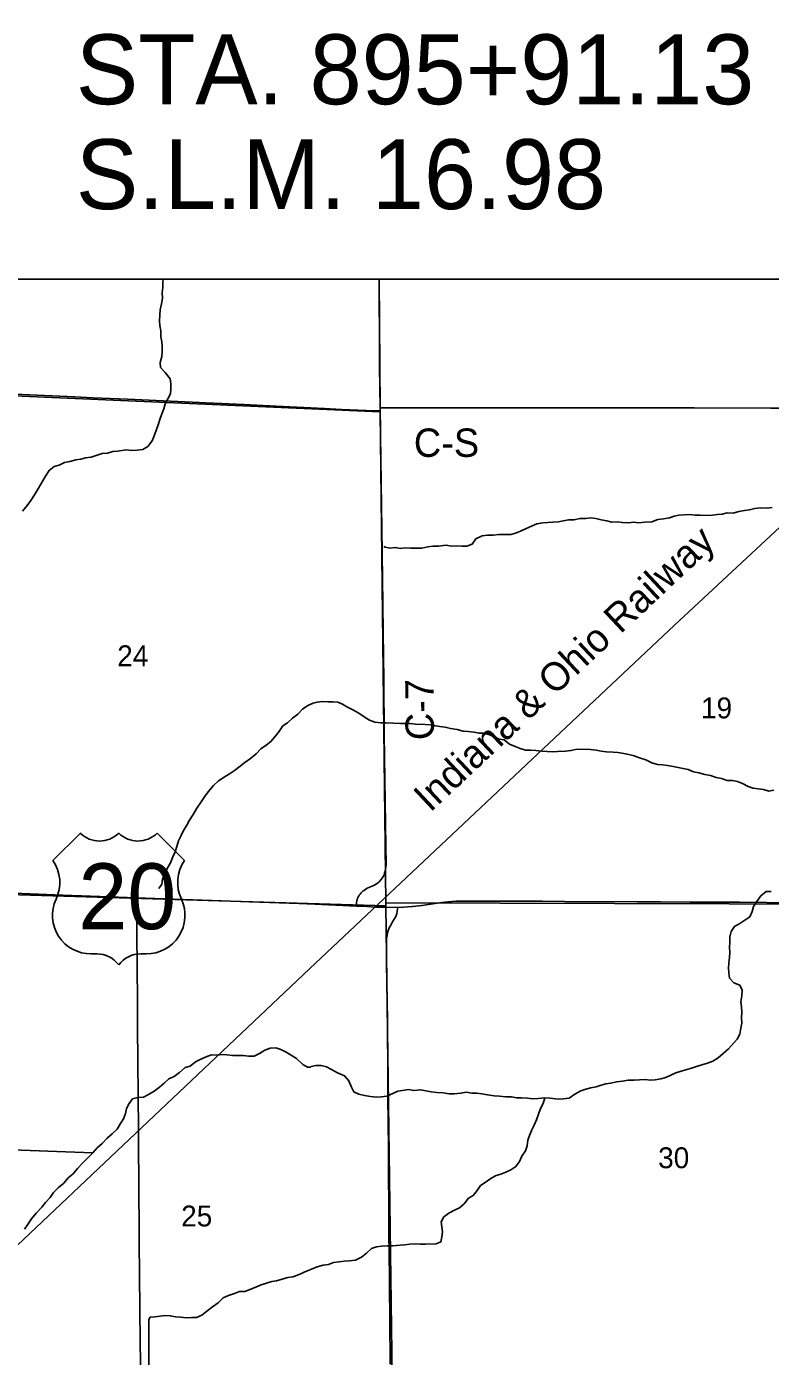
# Model space of a CAD drawing. Extents: x 0 to 34, y 0 to 22.
# Drawn here: x 28.195 to 29.684, y 16.699 to 19.362 of the extents above; entities that cross this region are included whole.
import ezdxf

# ---------------------------------------------------------------- set-up
doc = ezdxf.new("R2010")
doc.units = 0
for name, color, linetype in [('GM_X_County_Road', 7, 'Continuous'), ('GM_X_County_Road_Text', 7, 'Continuous'), ('GM_X_Minor_River', 7, 'Continuous'), ('GM_X_Rail_Line', 7, 'Continuous'), ('GM_X_Rail_Line_Text', 7, 'Continuous'), ('GM_X_Section', 7, 'Continuous'), ('GM_X_Section_Text', 7, 'Continuous'), ('GM_X_Township_Road', 7, 'Continuous'), ('GM_X_US_Location', 7, 'Continuous'), ('GM_X_US_Route', 7, 'Continuous'), ('GM_X_US_Shield', 7, 'Continuous'), ('SH_Data', 7, 'Continuous'), ('SH_Text', 7, 'Continuous')]:
    doc.layers.add(name, color=color, linetype=linetype)

msp = doc.modelspace()

# ---------------------------------------------------------------- linework, layer by layer
at = {"layer": 'GM_X_County_Road'}
msp.add_line((28.9028, 18.5928), (28.9028, 18.5988), dxfattribs=at)
for points in [[(28.9028, 18.5988), (28.9018, 18.6812), (28.9013, 18.7651), (28.9011, 18.7963), (28.9005, 18.8568)], [(27.9087, 18.6372), (27.993, 18.6341), (28.0955, 18.6295), (28.2911, 18.6207), (28.3284, 18.6191), (28.3967, 18.6161), (28.5551, 18.6091), (28.6296, 18.6055), (28.6948, 18.6022), (28.7911, 18.5974), (28.8252, 18.5957), (28.8749, 18.5932), (28.9028, 18.5928)], [(28.8551, 17.6011), (28.8551, 17.6049), (28.8554, 17.6079), (28.8558, 17.6111), (28.8561, 17.6128), (28.8572, 17.6158), (28.8582, 17.6184), (28.8593, 17.6203), (28.8608, 17.6226), (28.8626, 17.6249), (28.8647, 17.6275), (28.867, 17.6297), (28.8688, 17.6314), (28.8713, 17.6331), (28.874, 17.6348), (28.877, 17.6367), (28.88, 17.6382), (28.8836, 17.6398), (28.8867, 17.6409), (28.8895, 17.6421), (28.8918, 17.6432), (28.8943, 17.6447), (28.8968, 17.6465), (28.9001, 17.649), (28.905, 17.6542), (28.9071, 17.6569), (28.9089, 17.6601), (28.9095, 17.6612), (28.9108, 17.6638), (28.9118, 17.6668), (28.913, 17.6711), (28.9138, 17.6747), (28.9144, 17.679), (28.9145, 17.6835), (28.9143, 17.7215), (28.9137, 17.7648), (28.911, 17.9441), (28.9103, 18.0529), (28.9087, 18.1493), (28.908, 18.2053), (28.9067, 18.308), (28.9035, 18.5443), (28.9034, 18.563), (28.903, 18.5879), (28.9028, 18.5928)], [(28.9028, 18.5988), (28.9129, 18.5988), (28.9378, 18.599), (29.3452, 18.5987), (29.5317, 18.5988), (29.6841, 18.5981), (29.9546, 18.5979), (30.0457, 18.5989)], [(28.914, 17.5987), (28.8936, 17.5991), (28.8684, 17.6005), (28.8551, 17.6011)], [(28.9379, 17.5982), (28.937, 17.5981), (28.914, 17.5987)], [(28.9231, 16.6838), (28.9231, 16.7024), (28.9225, 16.7553), (28.9216, 16.8579), (28.9205, 16.9481), (28.9202, 16.9885), (28.9203, 16.9946), (28.9203, 17.0164), (28.9198, 17.0475), (28.9194, 17.1159), (28.9182, 17.2185), (28.9181, 17.2713), (28.9173, 17.3584), (28.9165, 17.4237), (28.9164, 17.4361), (28.9158, 17.4982), (28.9155, 17.5219), (28.9154, 17.53), (28.9156, 17.5358), (28.9165, 17.5424), (28.9183, 17.5501), (28.9211, 17.5574), (28.924, 17.563), (28.9276, 17.5694), (28.931, 17.5748), (28.9332, 17.5785), (28.935, 17.5818), (28.9358, 17.584), (28.9363, 17.586), (28.937, 17.5903), (28.9375, 17.5953), (28.9379, 17.5982)]]:
    msp.add_lwpolyline(points, dxfattribs=at)
at = {"layer": 'GM_X_Minor_River'}
for points in [[(28.4684, 18.8568), (28.4679, 18.8496), (28.4678, 18.8401), (28.4666, 18.8294), (28.4668, 18.8184), (28.4652, 18.8071), (28.4624, 18.7949), (28.4616, 18.7851), (28.4611, 18.7733), (28.4617, 18.7638), (28.4639, 18.7532), (28.4638, 18.741), (28.4656, 18.7312), (28.4666, 18.7213), (28.4665, 18.7114), (28.4656, 18.7015), (28.4625, 18.6894), (28.4627, 18.6799), (28.4721, 18.6696), (28.4822, 18.657), (28.484, 18.6471), (28.4835, 18.6368), (28.483, 18.627), (28.4726, 18.6066), (28.4695, 18.5967), (28.4656, 18.5865), (28.4616, 18.5752), (28.4585, 18.5646), (28.4546, 18.5532), (28.4503, 18.543), (28.446, 18.5325), (28.4376, 18.5215), (28.4276, 18.5152), (28.4166, 18.5138), (28.4045, 18.5135), (28.3947, 18.5147), (28.3772, 18.5119), (28.3677, 18.5116), (28.3571, 18.5079), (28.3461, 18.5073), (28.324, 18.4999), (28.313, 18.4989), (28.3035, 18.4959), (28.2936, 18.4945), (28.2818, 18.4912), (28.2708, 18.4894), (28.2601, 18.4842), (28.2499, 18.4813), (28.2403, 18.4734), (28.2326, 18.4617), (28.2233, 18.4459), (28.2168, 18.4345), (28.211, 18.4247), (28.2037, 18.413), (28.1963, 18.4029), (28.1867, 18.3916)], [(29.6876, 18.3992), (29.677, 18.3981), (29.6652, 18.3983), (29.6527, 18.3969), (29.6425, 18.3947), (29.6326, 18.3933), (29.6212, 18.3915), (29.6094, 18.3878), (29.5977, 18.3883), (29.5878, 18.3862), (29.5779, 18.3855), (29.5681, 18.3841), (29.5567, 18.3835), (29.5434, 18.3836), (29.5332, 18.3841), (29.523, 18.3849), (29.5116, 18.3847), (29.501, 18.3837), (29.4915, 18.3822), (29.482, 18.3785), (29.4702, 18.3768), (29.4588, 18.375), (29.447, 18.3702), (29.433, 18.3696), (29.4209, 18.3686), (29.4099, 18.3698), (29.4004, 18.3688), (29.3879, 18.3689), (29.3777, 18.3705), (29.3667, 18.3699), (29.3569, 18.3723), (29.3455, 18.3747), (29.3346, 18.3774), (29.3247, 18.3787), (29.3145, 18.3773), (29.3024, 18.377), (29.291, 18.3748), (29.28, 18.3742), (29.2697, 18.3728), (29.2591, 18.3702), (29.2485, 18.37), (29.2386, 18.3689), (29.2284, 18.3683), (29.2162, 18.3665), (29.2059, 18.3621), (29.1941, 18.3565), (29.1835, 18.3517), (29.1739, 18.348), (29.1641, 18.3454), (29.1516, 18.3452), (29.1406, 18.3449), (29.1288, 18.3439), (29.1174, 18.3437), (29.1068, 18.3426), (29.0946, 18.3363), (29.0869, 18.3258), (29.0762, 18.3221), (29.066, 18.3218), (29.0558, 18.3223), (29.0459, 18.322), (29.035, 18.3236), (29.0194, 18.3219), (29.008, 18.3217), (28.9982, 18.3202), (28.986, 18.3181), (28.9762, 18.3178), (28.9637, 18.3176), (28.9531, 18.3184), (28.9432, 18.3174), (28.933, 18.3194), (28.9227, 18.318), (28.9129, 18.3196), (28.9099, 18.3208)], [(28.7765, 18.0096), (28.7687, 18.0074), (28.7577, 18.0029), (28.7474, 17.9951), (28.7378, 17.9853), (28.7271, 17.9774), (28.7175, 17.968), (28.7079, 17.9617), (28.6999, 17.95), (28.6922, 17.9402), (28.6841, 17.9304), (28.6745, 17.9233), (28.6638, 17.9158), (28.6543, 17.9057), (28.6435, 17.8967), (28.6321, 17.8888), (28.6225, 17.8809), (28.6111, 17.8727), (28.6011, 17.8656), (28.5904, 17.8592), (28.5794, 17.8518), (28.5694, 17.8424), (28.5583, 17.83), (28.551, 17.8198), (28.5432, 17.8077), (28.5359, 17.7968), (28.5286, 17.7847), (28.5209, 17.773), (28.5158, 17.7628), (28.5089, 17.7523), (28.5046, 17.7421), (28.4992, 17.7315), (28.4956, 17.7202), (28.4925, 17.7096), (28.4878, 17.6997), (28.4828, 17.6873), (28.4762, 17.676), (28.4723, 17.6654), (28.4673, 17.6555), (28.466, 17.6449), (28.4595, 17.6363)], [(29.6913, 17.8334), (29.6811, 17.8313), (29.6701, 17.8344), (29.6599, 17.8357), (29.6493, 17.8373), (29.6395, 17.8404), (29.6286, 17.8466), (29.618, 17.8505), (29.6082, 17.8525), (29.5976, 17.8526), (29.5863, 17.8562), (29.5753, 17.8586), (29.5644, 17.8625), (29.5526, 17.8645), (29.5409, 17.8676), (29.53, 17.8697), (29.5194, 17.8743), (29.5092, 17.8767), (29.4892, 17.8803), (29.4778, 17.8823), (29.468, 17.884), (29.4578, 17.8844), (29.4465, 17.888), (29.4348, 17.8938), (29.4223, 17.8977), (29.4114, 17.902), (29.4008, 17.9044), (29.3906, 17.9068), (29.3789, 17.9084), (29.369, 17.9093), (29.3558, 17.9102), (29.3456, 17.911), (29.3354, 17.913), (29.324, 17.9147), (29.2971, 17.915), (29.2846, 17.9124), (29.274, 17.9114), (29.2577, 17.9104), (29.2474, 17.9098), (29.2372, 17.9103), (29.2266, 17.9111), (29.2145, 17.9128), (29.2043, 17.9133), (29.1937, 17.913), (29.1831, 17.9169), (29.1729, 17.9208), (29.1616, 17.9255), (29.1511, 17.9336), (29.1409, 17.9352), (29.1311, 17.9402), (29.1205, 17.9449), (29.1107, 17.9476), (29.1009, 17.9474), (29.091, 17.9494), (29.0789, 17.9506), (29.0691, 17.9515), (29.057, 17.9543), (29.0438, 17.9563), (29.0332, 17.9591), (29.0226, 17.9607), (29.0029, 17.9639), (28.9931, 17.9648), (28.9734, 17.965), (28.9632, 17.9666), (28.9533, 17.9667), (28.9435, 17.9665), (28.9298, 17.9674), (28.9139, 17.9679), (28.9041, 17.968), (28.8924, 17.9696), (28.8814, 17.9736), (28.8709, 17.9801), (28.86, 17.9871), (28.8491, 17.9936), (28.8374, 17.9994), (28.8276, 18.0056), (28.8178, 18.0091), (28.808, 18.01), (28.7977, 18.0101), (28.7871, 18.011), (28.7765, 18.0096), (28.7761, 18.0096)], [(29.6858, 17.6305), (29.6755, 17.6299), (29.6652, 17.6217), (29.6567, 17.6104), (29.6505, 17.6002), (29.6477, 17.59), (29.6427, 17.5794), (29.6228, 17.5659), (29.6125, 17.5604), (29.6059, 17.5498), (29.6032, 17.5392), (29.6026, 17.5282), (29.6025, 17.5184), (29.6028, 17.5077), (29.6023, 17.4979), (29.6006, 17.4873), (29.6005, 17.4767), (29.6007, 17.4672), (29.6025, 17.4569), (29.6107, 17.4473), (29.6228, 17.4423), (29.6276, 17.4324), (29.6267, 17.421), (29.625, 17.4093), (29.626, 17.399), (29.6267, 17.3884), (29.6265, 17.377), (29.6268, 17.3668), (29.6251, 17.3562), (29.6227, 17.3448), (29.6173, 17.3346), (29.6003, 17.3151), (29.5896, 17.3057), (29.5793, 17.2971), (29.5686, 17.2907), (29.5583, 17.2863), (29.5469, 17.283), (29.5359, 17.2797), (29.526, 17.2764), (29.5165, 17.2735), (29.5054, 17.2705), (29.4948, 17.2669), (29.4845, 17.2624), (29.4746, 17.258), (29.4647, 17.255), (29.4537, 17.2532), (29.4434, 17.2526), (29.4332, 17.2535), (29.4222, 17.2528), (29.4112, 17.2526), (29.3995, 17.2523), (29.3881, 17.2501), (29.3763, 17.2487), (29.3646, 17.2466), (29.3547, 17.2448), (29.3452, 17.2422), (29.3353, 17.2393), (29.3243, 17.2372), (29.3144, 17.2346)], [(28.3273, 17.1071), (27.9317, 17.1217), (27.9304, 17.2089), (27.9107, 17.2107), (27.9105, 17.3621)], [(28.7636, 17.2787), (28.7573, 17.2784), (28.7482, 17.2839), (28.7354, 17.2958), (28.7245, 17.3027), (28.7144, 17.3081), (28.7038, 17.3136), (28.6936, 17.3171), (28.6826, 17.3164), (28.6719, 17.3127), (28.6613, 17.306), (28.6506, 17.3001), (28.6392, 17.3002), (28.6282, 17.3018), (28.6184, 17.3019), (28.607, 17.302), (28.596, 17.3029), (28.5862, 17.3037), (28.5755, 17.3027), (28.5653, 17.3028), (28.5543, 17.2991), (28.5436, 17.2943), (28.5329, 17.2891), (28.5222, 17.2805), (28.5127, 17.2775), (28.5012, 17.2674), (28.4901, 17.2599), (28.4799, 17.2551), (28.4703, 17.2461), (28.4607, 17.2382), (28.4504, 17.2303), (28.4393, 17.2236), (28.429, 17.2184), (28.4173, 17.2178), (28.407, 17.2152), (28.4001, 17.2054), (28.3946, 17.1956), (28.3926, 17.1854), (28.3887, 17.1752), (28.3826, 17.1654), (28.376, 17.1544), (28.3664, 17.1446), (28.3561, 17.136), (28.3465, 17.1255), (28.3365, 17.1169), (28.3273, 17.1071), (28.3181, 17.0973), (28.307, 17.086), (28.2966, 17.0755), (28.2882, 17.065), (28.2782, 17.0567), (28.2694, 17.0462), (28.259, 17.0372), (28.2491, 17.0274), (28.2421, 17.0176), (28.2329, 17.0075), (28.2252, 16.9977), (28.2141, 16.986), (28.2049, 16.9747), (28.1983, 16.9646), (28.191, 16.954)], [(29.3144, 17.2346), (29.3049, 17.2309), (29.2927, 17.2246), (29.2812, 17.216), (29.2694, 17.215), (29.2592, 17.2143), (29.2429, 17.2164), (29.2323, 17.2169), (29.2194, 17.2155), (29.2088, 17.2148), (29.1978, 17.2161), (29.1857, 17.217), (29.1759, 17.2171), (29.1656, 17.2187), (29.1547, 17.2192), (29.1418, 17.2201), (29.1308, 17.2213), (29.1176, 17.223), (29.1062, 17.225), (29.0964, 17.2263), (29.0866, 17.2264), (29.0752, 17.228), (29.0646, 17.2262), (29.0509, 17.2248), (29.0411, 17.2253), (29.029, 17.227), (29.0161, 17.2275), (29.0047, 17.2291), (28.9945, 17.2307), (28.9836, 17.2331), (28.9699, 17.2314), (28.9593, 17.2334), (28.9476, 17.2316), (28.9381, 17.2306), (28.9282, 17.2257), (28.916, 17.2202), (28.9053, 17.2188), (28.8958, 17.2181), (28.8837, 17.2198), (28.8713, 17.2218), (28.8603, 17.2246), (28.8498, 17.2292), (28.845, 17.2395), (28.8398, 17.2513), (28.8316, 17.2609), (28.8176, 17.2671), (28.8056, 17.2737), (28.7954, 17.2791), (28.7845, 17.2815), (28.7743, 17.282), (28.7644, 17.2794), (28.7636, 17.2787)], [(29.2323, 17.2169), (29.2291, 17.2059), (29.2241, 17.1953), (29.2198, 17.1844), (29.2155, 17.1727), (29.2112, 17.1625), (29.2065, 17.1527), (29.2018, 17.1417), (29.1983, 17.1319), (29.197, 17.1209), (29.1935, 17.1107), (29.1865, 17.1001), (29.1818, 17.0892), (29.1745, 17.0794), (29.1646, 17.0727), (29.1543, 17.0682), (29.1444, 17.0642), (29.1349, 17.0612), (29.1249, 17.0564), (29.115, 17.0489), (29.1035, 17.0411), (29.0973, 17.0313), (29.0893, 17.0215), (29.0797, 17.0159), (29.0712, 17.005), (29.0617, 16.9964), (29.0514, 16.9923), (29.0403, 16.986), (29.0304, 16.9785), (29.0249, 16.9683), (29.0263, 16.9584), (29.0277, 16.9489), (29.0264, 16.9383), (29.0244, 16.9285), (29.0149, 16.9244), (28.9937, 16.9239), (28.9838, 16.9236), (28.9732, 16.9245), (28.9622, 16.9242), (28.9524, 16.9228), (28.9429, 16.9221), (28.9285, 16.9208), (28.9171, 16.9205), (28.9053, 16.9199), (28.8955, 16.9185), (28.8856, 16.9151), (28.8756, 16.9061), (28.8656, 16.8979), (28.8531, 16.892), (28.8409, 16.8902), (28.8307, 16.8899), (28.8208, 16.8885), (28.8091, 16.8871), (28.7995, 16.883), (28.7885, 16.8816), (28.7767, 16.8787)], [(28.7508, 16.868), (28.7469, 16.8661), (28.7374, 16.8617), (28.7279, 16.8584), (28.718, 16.8569), (28.6952, 16.8503), (28.6857, 16.8493), (28.6648, 16.8427), (28.6552, 16.8382), (28.6438, 16.8338), (28.6316, 16.829), (28.6214, 16.8291), (28.6111, 16.825), (28.5993, 16.8213), (28.5883, 16.8165), (28.5787, 16.8067), (28.5668, 16.7981), (28.5561, 16.7899), (28.5458, 16.7816), (28.5351, 16.7772), (28.5249, 16.7769), (28.5143, 16.7766), (28.504, 16.7775), (28.4927, 16.7784), (28.4825, 16.7804), (28.4715, 16.7808), (28.462, 16.7798), (28.4514, 16.7784), (28.4424, 16.7776), (28.4399, 16.7728)], [(28.7767, 16.8787), (28.7508, 16.868)], [(28.4399, 16.7728), (28.4392, 16.4063), (28.4153, 16.4069), (28.4126, 16.1644)]]:
    msp.add_lwpolyline(points, dxfattribs=at)
at = {"layer": 'GM_X_Rail_Line'}
msp.add_lwpolyline([(27.0345, 15.3175), (27.0356, 15.4259), (27.0494, 15.5562), (27.0656, 15.6449), (27.0886, 15.7152), (27.1197, 15.8028), (27.1531, 15.872), (27.1854, 15.9273), (27.2223, 15.9838), (27.2614, 16.0437), (27.3144, 16.1048), (27.4089, 16.2005), (27.94, 16.6983), (28.7611, 17.4753), (29.4921, 18.1638), (30.1262, 18.7537), (30.3167, 18.9329)], dxfattribs=at)
at = {"layer": 'GM_X_Section'}
for points in [[(28.9007, 18.8568), (28.9028, 18.5982), (28.9031, 18.5906), (27.9094, 18.6339), (27.9, 19.6399), (28.1535, 19.6259)], [(29.8322, 19.5929), (30.0362, 19.5914), (30.0497, 18.599), (28.9028, 18.5982), (28.9007, 18.8568)]]:
    msp.add_lwpolyline(points, dxfattribs=at)
for points in [[(27.9094, 18.6339), (28.9031, 18.5906), (28.914, 17.6074), (28.9139, 17.6013), (27.9132, 17.6317)], [(28.9028, 18.5982), (30.0497, 18.599), (30.0593, 17.6044), (28.914, 17.6074), (28.9031, 18.5906)], [(27.9132, 17.6317), (28.9139, 17.6013), (28.9274, 16.6074), (28.9273, 16.6021), (27.9213, 16.6311)], [(28.914, 17.6074), (30.0593, 17.6044), (30.0675, 16.617), (28.9274, 16.6074), (28.9139, 17.6013)]]:
    msp.add_lwpolyline(points, close=True, dxfattribs=at)
at = {"layer": 'GM_X_Township_Road'}
msp.add_lwpolyline([(28.4231, 16.6192), (28.4229, 16.6313), (28.4227, 16.681), (28.4217, 16.7868), (28.4209, 16.8708), (28.4205, 16.9205), (28.4195, 17.0667), (28.4192, 17.1009), (28.4187, 17.1538), (28.4171, 17.359), (28.4168, 17.4026), (28.4164, 17.4865), (28.4158, 17.5363), (28.4152, 17.6079), (28.4152, 17.6177)], dxfattribs=at)
at = {"layer": 'GM_X_US_Route'}
msp.add_line((28.7727, 17.6045), (28.8551, 17.6011), dxfattribs=at)
for points in [[(26.9096, 17.635), (26.9581, 17.635), (27.0332, 17.6348), (27.095, 17.6348), (27.1262, 17.6349), (27.3284, 17.6352), (27.3938, 17.6349), (27.4119, 17.6349), (27.4218, 17.635), (27.4591, 17.6353), (27.5214, 17.6354), (27.7516, 17.6357), (27.8232, 17.6358), (27.873, 17.636), (27.916, 17.6355), (27.9507, 17.6348), (28.1529, 17.6272), (28.2679, 17.623), (28.4152, 17.6177), (28.4514, 17.6164), (28.6411, 17.6096), (28.7406, 17.6059), (28.7727, 17.6045)], [(28.9669, 17.5999), (28.9679, 17.6), (28.9863, 17.6023), (29.0263, 17.6083), (29.0386, 17.6096), (29.0542, 17.6106), (29.0759, 17.611), (29.1256, 17.611), (29.1909, 17.6107), (29.2281, 17.6106), (29.2716, 17.6102), (29.4176, 17.6096), (29.4642, 17.6094), (29.5232, 17.609), (29.6225, 17.6086), (29.7312, 17.6076)], [(28.8551, 17.6011), (28.8684, 17.6005), (28.8936, 17.5991), (28.914, 17.5987)], [(28.914, 17.5987), (28.937, 17.5981), (28.9379, 17.5982)], [(28.9379, 17.5982), (28.9493, 17.5985), (28.9669, 17.5999)]]:
    msp.add_lwpolyline(points, dxfattribs=at)
at = {"layer": 'GM_X_US_Shield'}
for p, q in [((28.3025, 17.747), (28.2475, 17.6921)), ((28.5112, 17.6921), (28.4563, 17.747)), ((28.3244, 17.5053), (28.3354, 17.5053)), ((28.4233, 17.5053), (28.4343, 17.5053))]:
    msp.add_line(p, q, dxfattribs=at)
for centre, radius, start, end in [((28.3409, 17.7862), 0.0549, 225.573, 314.427), ((28.4178, 17.7862), 0.0549, 225.573, 314.427), ((28.1845, 17.648), 0.0769, 334.5471, 35.0009), ((28.5742, 17.648), 0.0769, 144.9991, 205.4529), ((28.3236, 17.5822), 0.0769, 154.8319, 270.6383), ((28.4352, 17.5822), 0.0769, 269.3617, 25.1681), ((28.3354, 17.4504), 0.0549, 36.8699, 90), ((28.4233, 17.4504), 0.0549, 90, 143.1301)]:
    msp.add_arc(centre, radius, start, end, dxfattribs=at)
at = {"layer": 'SH_Data'}
msp.add_lwpolyline([(28.1535, 19.6968), (29.8322, 19.6968), (29.8322, 18.8568), (28.1535, 18.8568)], close=True, dxfattribs=at)

# ---------------------------------------------------------------- texts
at = {"layer": 'GM_X_County_Road_Text'}
for s, rotation, p in [('C-S', 0, (28.9702, 18.5006)), ('C-7', 90.4581, (29.0106, 17.9334))]:
    msp.add_text(s, height=0.05682, rotation=rotation, dxfattribs=at).set_placement(p)
at = {"layer": 'GM_X_Rail_Line_Text'}
msp.add_text('Indiana & Ohio Railway', height=0.056629, rotation=43.1881, dxfattribs=at).set_placement((29.0031, 17.7873))
at = {"layer": 'GM_X_Section_Text'}
for s, p in [('24', (28.3764, 18.0813)), ('19', (29.5452, 17.9769)), ('30', (29.4594, 17.076)), ('25', (28.5044, 16.9594))]:
    msp.add_text(s, height=0.04186, rotation=0, dxfattribs=at).set_placement(p)
at = {"layer": 'GM_X_US_Location'}
for s in ['0', '/']:
    msp.add_text(s, height=0.000189, dxfattribs=at).set_placement((28.3793, 17.6196))
msp.add_text('20', height=0.000189, rotation=0, dxfattribs=at).set_placement((28.3402, 17.5804))
at = {"layer": 'GM_X_US_Shield'}
msp.add_text('20', height=0.13184, dxfattribs=at).set_placement((28.2985, 17.5547))
at = {"layer": 'SH_Text'}
for s, p in [('STA. 895+91.13', (28.2935, 19.2068)), ('S.L.M. 16.98', (28.2935, 18.9968))]:
    msp.add_text(s, height=0.14, dxfattribs=at).set_placement(p)

doc.saveas('drawing.dxf')
